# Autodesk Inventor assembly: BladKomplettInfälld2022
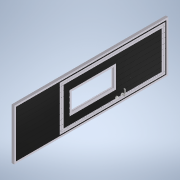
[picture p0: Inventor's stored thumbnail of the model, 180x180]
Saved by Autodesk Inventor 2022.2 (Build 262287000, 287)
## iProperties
Created: 2022-02
Part Number: BladKomplettInfälld2022
Document SubType Name: Assembly
Designer: cl
Author: cl
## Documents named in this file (8)
- G:\AutoCad\Carl Lund\3D-modeller systemlösningar\3D-modell-systemlösning-2022\Parts\BladKomplettInfälld2022.iam
- G:\AutoCad\Carl Lund\3D-modeller systemlösningar\3D-modell-systemlösning-2022\Styrande.iam
- G:\AutoCad\Carl Lund\3D-modeller systemlösningar\3D-modell-systemlösning-2022\Parts\AluKarmBlad.ipt
- G:\AutoCad\Carl Lund\3D-modeller systemlösningar\3D-modell-systemlösning-2022\Parts\BladInfäld.ipt
- G:\AutoCad\Carl Lund\3D-modeller systemlösningar\3D-modell-systemlösning-2022\Parts\Fönsterkarm.ipt
- G:\AutoCad\Carl Lund\3D-modeller systemlösningar\3D-modell-systemlösning-2022\Parts\InfälldGångDörrAlu.ipt
- G:\AutoCad\Carl Lund\3D-modeller systemlösningar\3D-modell-systemlösning-2022\Parts\DörrHAndtag-V.ipt
- G:\AutoCad\Carl Lund\3D-modeller systemlösningar\3D-modell-systemlösning-2022\Parts\GångJärnInf.ipt
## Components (8 placed, 6 different names)
1. BladInfäld:1 — Mate:1, Mate:2, Flush:1, Mate:3, Flush:2, Flush:3, Mate:4
2. AluKarmBlad:1 — Mate:3, Flush:2, Flush:3, Flush:6, Flush:7, Flush:11, Flush:12, Mate:5, Mate:7, Mate:11, Mate:14, Mate:15, Mate:16
3. Fönsterkarm:1 — Mate:4, Flush:6, Flush:7, Flush:8, Flush:9, Flush:10
4. Fönsterkarm:2 — Flush:8, Flush:9, Flush:10
5. InfälldGångDörrAlu:1 — Flush:11, Flush:12, Mate:5, Flush:13, Flush:14, Mate:12, Mate:13
6. DörrHAndtag-V:1 — Mate:7, Mate:13, Mate:14, Mate:15, Mate:16
7. GångJärnInf:1 — Flush:13, Mate:10, Mate:11, Mate:12
8. GångJärnInf:2 — Mate:10, Flush:14
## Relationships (25: Mate 13, Flush 12)
- Mate:1: BladInfäld:1
- Mate:2: BladInfäld:1
- Flush:1: BladInfäld:1
- Mate:3: BladInfäld:1 ↔ AluKarmBlad:1
- Flush:2: BladInfäld:1 ↔ AluKarmBlad:1
- Flush:3: BladInfäld:1 ↔ AluKarmBlad:1
- Mate:4: BladInfäld:1 ↔ Fönsterkarm:1
- Flush:6: AluKarmBlad:1 ↔ Fönsterkarm:1
- Flush:7: AluKarmBlad:1 ↔ Fönsterkarm:1
- Flush:8: Fönsterkarm:1 ↔ Fönsterkarm:2
- Flush:9: Fönsterkarm:1 ↔ Fönsterkarm:2
- Flush:10: Fönsterkarm:1 ↔ Fönsterkarm:2
- Flush:11: AluKarmBlad:1 ↔ InfälldGångDörrAlu:1
- Flush:12: AluKarmBlad:1 ↔ InfälldGångDörrAlu:1
- Mate:5: AluKarmBlad:1 ↔ InfälldGångDörrAlu:1
- Mate:7: AluKarmBlad:1 ↔ DörrHAndtag-V:1
- Flush:13: InfälldGångDörrAlu:1 ↔ GångJärnInf:1
- Mate:10: GångJärnInf:1 ↔ GångJärnInf:2
- Flush:14: InfälldGångDörrAlu:1 ↔ GångJärnInf:2
- Mate:11: AluKarmBlad:1 ↔ GångJärnInf:1
- Mate:12: InfälldGångDörrAlu:1 ↔ GångJärnInf:1
- Mate:13: InfälldGångDörrAlu:1 ↔ DörrHAndtag-V:1
- Mate:14: AluKarmBlad:1 ↔ DörrHAndtag-V:1
- Mate:15: AluKarmBlad:1 ↔ DörrHAndtag-V:1
- Mate:16: AluKarmBlad:1 ↔ DörrHAndtag-V:1
## Named parameters: BladBredd = 987.5 mm, Fönsterhöjd = 862 mm, Blad2 = 1012.5 mm, Blad3 = 0, Blad4 = 0, Blad5 = 1012.5 mm, Blad6 = 2025 mm, MGJ12Djup = 0, MGJ12Bredd = 0, MGJ2Djup = 0, MGJ2Bredd = 5012.5 mm, MGJ56Djup = 0, MGJ56Bredd = 0, MGJ23Djup = 48 mm, MGJ45Djup = 48 mm, GarageRegel5 = 0, GarageRegel6 = 0, Styrrulle2Djup = 0, FönsterhöjdStyrning = 862 mm, FönsterKarm = 54 mm, AndraGlasraden = 0, BrösthöjdStyrning2 = 0.0001 mm, InfälldGångDörr = 0, Infälldstyr = 1012.5 mm
